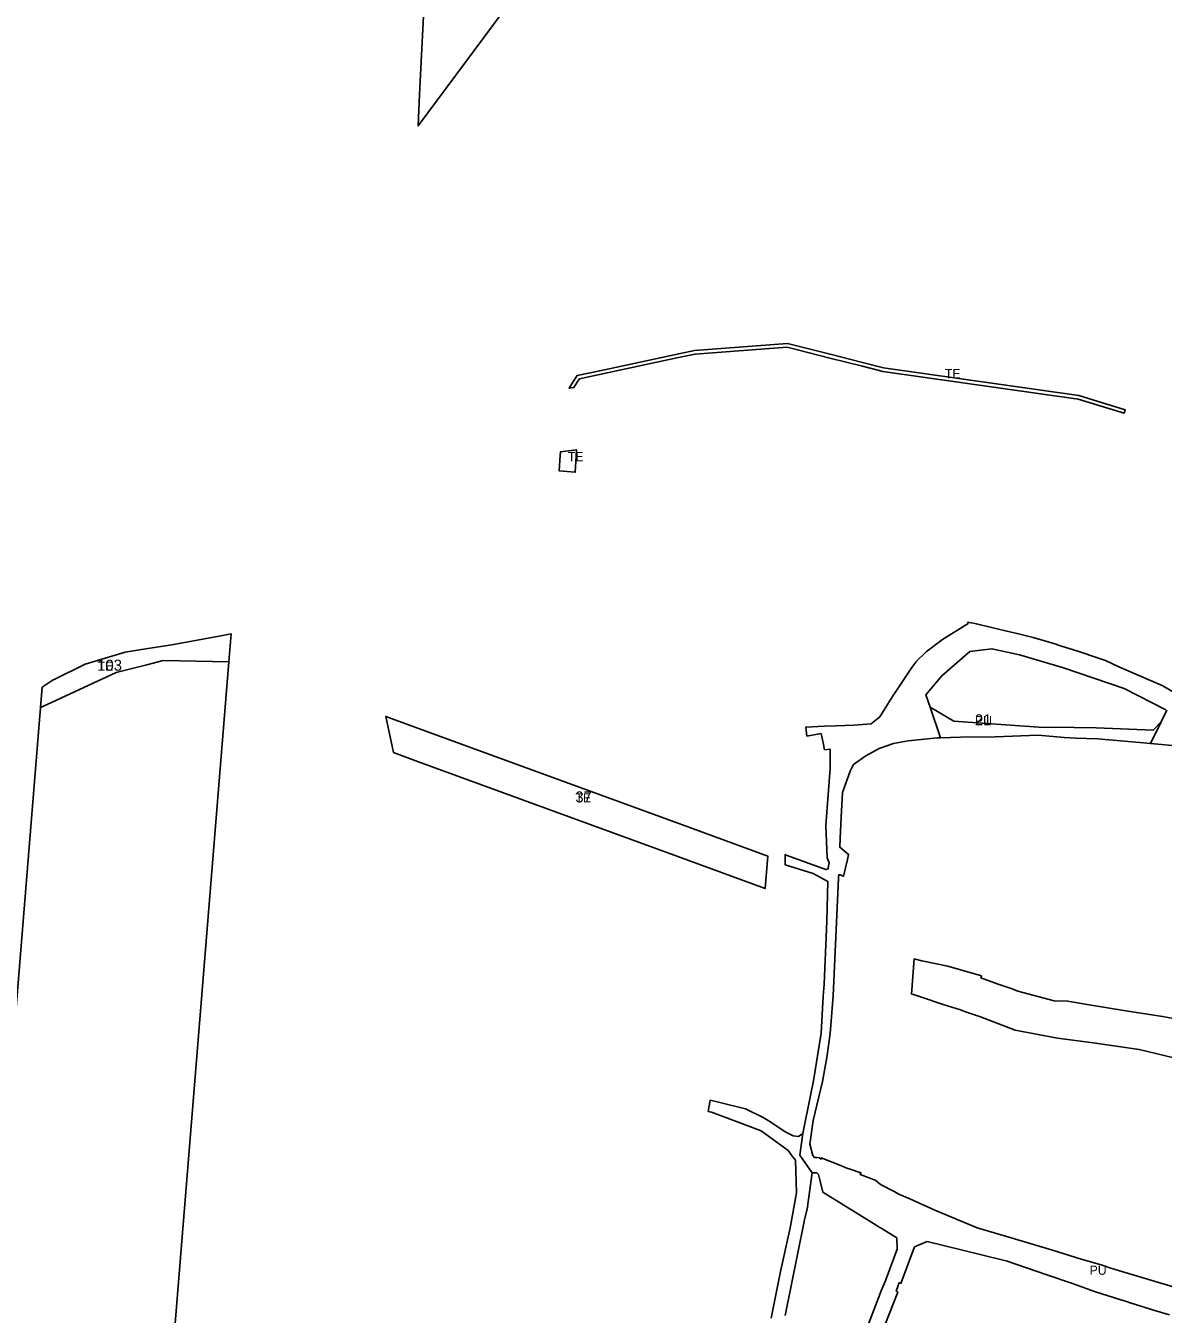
# Model space of a CAD drawing. Extents: x -545758 to -541641, y -1153152 to -1149975.
# Drawn here: x -544753 to -544135, y -1151383 to -1150683 of the extents above; entities that cross this region are included whole.
import ezdxf

# ---------------------------------------------------------------- set-up
doc = ezdxf.new("R2010")
doc.units = 0
for name, color, linetype in [('90400013', 7, 'Continuous'), ('90400023', 7, 'Continuous'), ('90450013', 7, 'Continuous'), ('90450023', 7, 'Continuous'), ('ID_navrh', 7, 'Continuous')]:
    doc.layers.add(name, color=color, linetype=linetype)

msp = doc.modelspace()

# ---------------------------------------------------------------- linework, layer by layer
at = {"layer": '90400013'}
for points in [[(-544339.08, -1150857.24), (-544389.1, -1150860.97), (-544398.09, -1150862.89), (-544441.01, -1150872.08), (-544451.94, -1150874.42), (-544453.08, -1150876.18), (-544454.93, -1150879.06), (-544455.39, -1150879.13), (-544457.14, -1150879.42), (-544457.6, -1150879.49), (-544455.47, -1150876.18), (-544453.18, -1150872.64), (-544440.91, -1150870.01), (-544397.99, -1150860.82), (-544389.37, -1150858.98), (-544338.91, -1150855.23), (-544315.7, -1150861.08), (-544298.04, -1150865.53), (-544290.38, -1150867.46), (-544286.78, -1150868.37), (-544180.51, -1150883.46), (-544155.31, -1150891.22), (-544155.87, -1150893.02), (-544180.94, -1150885.41), (-544287.16, -1150870.34), (-544290.46, -1150869.51), (-544298.12, -1150867.58), (-544315.79, -1150863.12)], [(-544453.72, -1150916.42), (-544454.2, -1150925.15), (-544462.92, -1150924.5), (-544462.43, -1150916.09), (-544462.3, -1150914.11), (-544453.51, -1150912.96)]]:
    msp.add_lwpolyline(points, close=True, dxfattribs=at)
at = {"layer": '90400023'}
for points in [[(-544535.69, -1150656.11), (-544474.535, -1150647.062), (-544474.888, -1150647.749), (-544475.385, -1150648.687), (-544475.891, -1150649.62), (-544476.407, -1150650.548), (-544476.933, -1150651.471), (-544477.468, -1150652.388), (-544478.013, -1150653.3), (-544478.568, -1150654.206), (-544479.133, -1150655.105), (-544479.706, -1150655.999), (-544480.289, -1150656.886), (-544480.881, -1150657.767), (-544481.482, -1150658.641), (-544482.092, -1150659.508), (-544482.71, -1150660.369), (-544483.338, -1150661.223), (-544539.608, -1150736.946), (-544538.78, -1150719.82), (-544535.83, -1150659.11)], [(-544646.83, -1151014.09), (-544641.174, -1151013.082), (-544642.403, -1151028.226), (-544678.11, -1151027.51), (-544687.067, -1151029.768), (-544703.7, -1151033.96), (-544738.859, -1151050.292), (-544744.745, -1151053.026), (-544743.853, -1151042.034), (-544737.883, -1151038.026), (-544737.8, -1151037.97), (-544720.48, -1151029.53), (-544698.76, -1151022.98), (-544686.373, -1151021.047), (-544686.373, -1151021.047), (-544673.39, -1151019.02)], [(-544398.393, -1151134.104), (-544541.325, -1151081.794), (-544552.912, -1151077.549), (-544557.159, -1151057.889), (-544535.48, -1151065.83), (-544535.48, -1151065.83), (-544392.55, -1151118.14), (-544349.539, -1151133.883), (-544351.093, -1151151.417)]]:
    msp.add_lwpolyline(points, close=True, dxfattribs=at)
msp.add_lwpolyline([(-544841.973, -1152250.685), (-544744.745, -1151053.026), (-544738.859, -1151050.292), (-544703.7, -1151033.96), (-544687.067, -1151029.768), (-544678.11, -1151027.51), (-544642.403, -1151028.226), (-544742.287, -1152258.607)], dxfattribs=at)
at = {"layer": '90450013'}
for points in [[(-544296.52, -1151392.31), (-544289.48, -1151373.85), (-544288.03, -1151370.05), (-544285.86, -1151365.099), (-544285.76, -1151365.11), (-544285.19, -1151363.57), (-544279.26, -1151347.52), (-544279.49, -1151341.29), (-544287.98, -1151336.05), (-544288.98, -1151335.43), (-544290.66, -1151334.39), (-544319.64, -1151316.49), (-544321.15, -1151310.42), (-544322.04, -1151306.84), (-544322.89, -1151306.03), (-544323.14, -1151306.03), (-544324.13, -1151306.01), (-544325.52, -1151305.99), (-544332.09, -1151296.26), (-544330.54, -1151284.54), (-544326.16, -1151263.08), (-544324.7, -1151255.9), (-544320.53, -1151230.04), (-544319.5, -1151209.97), (-544319, -1151203.45), (-544317.52, -1151169.14), (-544317.04, -1151147.53), (-544324.86, -1151143.2), (-544340.13, -1151138.59), (-544340.12, -1151137.33), (-544340.12, -1151136.85), (-544340.09, -1151133.08), (-544340.09, -1151132.86), (-544339.59, -1151133.35), (-544318.04, -1151141.16), (-544316.85, -1151140.73), (-544316.52, -1151139.06), (-544316.18, -1151137.4), (-544317.35, -1151134.76), (-544317.99, -1151117.14), (-544315.73, -1151086.26), (-544315.73, -1151075.6), (-544318.73, -1151076.05), (-544319.5, -1151072.26), (-544320.64, -1151067.23), (-544328.3, -1151068.58), (-544328.84, -1151063.72), (-544318.75, -1151063.23), (-544312.53, -1151063.09), (-544302.75, -1151062.65), (-544293.42, -1151061.86), (-544288.69, -1151058.11), (-544286.37, -1151054.32), (-544281.81, -1151047.05), (-544271.34, -1151031.38), (-544269.15, -1151028.43), (-544269.25, -1151028.35), (-544263.54, -1151022.86), (-544254.64, -1151016.06), (-544240.68, -1151007.33), (-544240.8, -1151006.59), (-544236.21, -1151007.63), (-544227.99, -1151009.48), (-544217.31, -1151012.11), (-544214.12, -1151012.89), (-544205.37, -1151014.99), (-544192.34, -1151018.83), (-544192.4, -1151019.04), (-544181.06, -1151022.45), (-544169.93, -1151026.19), (-544166.12, -1151027.56), (-544158.87, -1151030.91), (-544148.39, -1151035.46), (-544135.01, -1151041.31), (-544040.31, -1151097.11)], [(-544133.31, -1151054.25), (-544155.85, -1151042.75), (-544188.98, -1151031.43), (-544212.83, -1151024.4), (-544227.79, -1151021.07), (-544239.88, -1151022.55), (-544255.06, -1151035.76), (-544263.64, -1151046.09), (-544261.39, -1151052.79), (-544255.79, -1151069.46), (-544257.32, -1151069.5), (-544273.39, -1151071.2), (-544281.31, -1151072.64), (-544289.05, -1151075.26), (-544296.35, -1151079.23), (-544302.97, -1151083.97), (-544304.91, -1151087.65), (-544308.93, -1151099.17), (-544309.66, -1151112.71), (-544310.22, -1151123.99), (-544310.47, -1151128.98), (-544305.65, -1151132.88), (-544306.28, -1151135.64), (-544308.38, -1151144.78), (-544310.81, -1151143.81), (-544311.08, -1151144.88), (-544311.16, -1151145.77), (-544314.11, -1151209.76), (-544315.77, -1151230.23), (-544317.56, -1151243.24), (-544319.79, -1151256.39), (-544324.93, -1151277.46), (-544326.79, -1151290.45), (-544325.19, -1151296.57), (-544324.28, -1151297.64), (-544324.02, -1151297.65), (-544323, -1151297.7), (-544321.55, -1151297.77), (-544320.65, -1151298.6), (-544320.51, -1151297.8), (-544310.36, -1151301.85), (-544306.65, -1151303.34), (-544304.91, -1151303.91), (-544298.99, -1151306.02), (-544299.32, -1151306.86), (-544293.65, -1151309.1), (-544290.82, -1151310.16), (-544288.41, -1151312.26), (-544280.95, -1151316.12), (-544278.04, -1151317.64), (-544272.39, -1151320.03), (-544258.81, -1151326.24), (-544235.8, -1151335.76), (-544217.39, -1151341.34), (-544194.96, -1151347.93), (-544179.22, -1151352.91), (-544168.36, -1151356.04), (-544162.64, -1151357.91), (-544143.24, -1151363.76), (-544125.62, -1151369.07)], [(-544125.96, -1151074.03), (-544141.57, -1151072.66), (-544135.83, -1151060.82), (-544132.77, -1151054.51)], [(-544128.88, -1151243.44), (-544147.79, -1151238.88), (-544172.85, -1151235.23), (-544192.11, -1151232.82), (-544215.15, -1151228.39), (-544233.95, -1151221.19), (-544242.14, -1151218.52), (-544244.94, -1151217.45), (-544254.27, -1151214.4), (-544266.53, -1151210.37), (-544270.44, -1151209), (-544271.45, -1151208.83), (-544270.06, -1151189.65), (-544265.8, -1151190.64), (-544251.76, -1151193.56), (-544233.48, -1151198.92), (-544233.8, -1151200.03), (-544224.38, -1151203.33), (-544216.85, -1151206), (-544213.68, -1151207.15), (-544194, -1151212.55), (-544186.63, -1151212.66), (-544184.48, -1151212.99), (-544174.98, -1151214.61), (-544155.03, -1151217.91), (-544135.07, -1151220.92), (-544119.1, -1151223.83)], [(-544131.37, -1151383.21), (-544138.76, -1151381.03), (-544152.74, -1151376.56), (-544154.75, -1151375.93), (-544157.71, -1151374.97), (-544171.97, -1151370.38), (-544184.06, -1151366.1), (-544197.92, -1151361.47), (-544220.07, -1151353.81), (-544221.72, -1151353.39), (-544243.82, -1151347.99), (-544263.04, -1151343.3), (-544269.78, -1151346.21), (-544277.27, -1151366.08), (-544278.29, -1151365.66), (-544278.79, -1151367.18), (-544278.97, -1151367.71), (-544279.14, -1151368.23), (-544279.78, -1151370.16), (-544279.01, -1151370.9), (-544293.39, -1151407.59)]]:
    msp.add_lwpolyline(points, dxfattribs=at)
at = {"layer": '90450023'}
msp.add_lwpolyline([(-544182.27, -1151069.63), (-544188.57, -1151069.43), (-544202.6, -1151068.01), (-544226.12, -1151068.98), (-544244.82, -1151069.16), (-544255.79, -1151069.46), (-544261.39, -1151052.79), (-544248.55, -1151060.53), (-544202.28, -1151063.65), (-544183.14, -1151063.96), (-544171.16, -1151064.15), (-544140.09, -1151065.42), (-544135.83, -1151060.82), (-544141.57, -1151072.66), (-544147.35, -1151072.15), (-544170.42, -1151070.01)], close=True, dxfattribs=at)
msp.add_lwpolyline([(-544347.81, -1151384.94), (-544342.65, -1151359.51), (-544337.5, -1151335.87), (-544333.93, -1151316.81), (-544334.45, -1151298.99), (-544336.38, -1151296.81), (-544338.53, -1151293.83), (-544353.12, -1151283.1), (-544361.282, -1151280.032), (-544380.12, -1151272.95), (-544381.96, -1151272.53), (-544380.945, -1151266.525), (-544376.33, -1151267.55), (-544361.72, -1151271.16), (-544352.01, -1151275.9), (-544349.44, -1151277.57), (-544339.82, -1151283.83), (-544335.78, -1151285.78), (-544332.89, -1151286.27), (-544330.54, -1151284.54), (-544332.09, -1151296.26), (-544325.52, -1151305.99), (-544328.22, -1151325.77), (-544329.71, -1151331.38), (-544329.9, -1151332.33), (-544340.23, -1151383.48)], dxfattribs=at)

# ---------------------------------------------------------------- texts
at = {"layer": '90400013'}
for rotation, p in [(360, (-544253.366, -1150874.125)), (0, (-544458.215, -1150919.213))]:
    msp.add_text('TE', height=5, rotation=rotation, dxfattribs=at).set_placement(p)
at = {"layer": '90400023'}
for p in [(-544713.908, -1151033.054), (-544454.133, -1151104.653)]:
    msp.add_text('TE', height=5, rotation=0, dxfattribs=at).set_placement(p)
at = {"layer": '90450013'}
msp.add_text('PU', height=5, rotation=0, dxfattribs=at).set_placement((-544174.75, -1151361.35))
at = {"layer": '90450023'}
msp.add_text('PU', height=5, rotation=360, dxfattribs=at).set_placement((-544237.025, -1151062.725))
at = {"layer": 'ID_navrh'}
for s, rotation, p in [('103', 0, (-544713.908, -1151033.054)), ('21', 360, (-544237.025, -1151062.725)), ('37', 360, (-544454.133, -1151104.653))]:
    msp.add_text(s, height=6, rotation=rotation, dxfattribs=at).set_placement(p)

doc.saveas('drawing.dxf')
